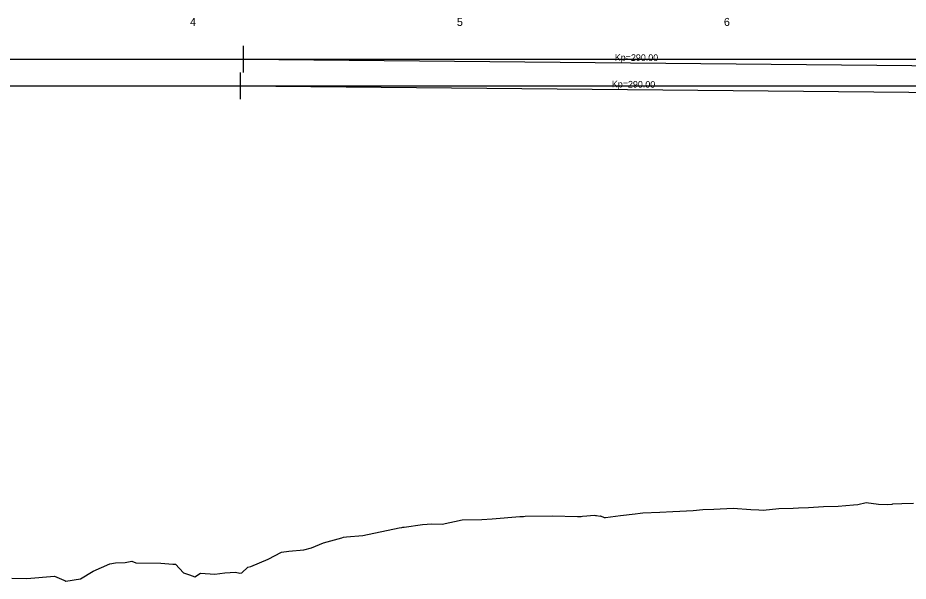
# Model space of a CAD drawing. Extents: x 6531046 to 6533341, y 5514966 to 5518007.
# Drawn here: x 6532180.6 to 6532514.2, y 5516249.9 to 5516461 of the extents above; entities that cross this region are included whole.
import ezdxf

# ---------------------------------------------------------------- set-up
doc = ezdxf.new("R2010")
doc.units = 0
for name, color, linetype in [('IR_default', 7, 'Continuous'), ('TOR_PROF-tabelka-geometria T1', 7, 'Continuous'), ('TOR_PROF-tabelka-kilometracja', 7, 'Continuous')]:
    doc.layers.add(name, color=color, linetype=linetype)

msp = doc.modelspace()

# ---------------------------------------------------------------- linework, layer by layer
at = {"layer": 'IR_default'}
msp.add_lwpolyline([(6532178.4, 5516251.04), (6532183.99, 5516250.9), (6532194.36, 5516251.73), (6532197.81, 5516250.25), (6532198.22, 5516250.12), (6532198.67, 5516249.9), (6532204.05, 5516250.79), (6532204.09, 5516250.8), (6532204.11, 5516250.81), (6532208.83, 5516253.7), (6532215.05, 5516256.47), (6532217.25, 5516256.73), (6532220.8, 5516256.88), (6532223.33, 5516257.47), (6532224.88, 5516256.79), (6532234.24, 5516256.65), (6532238.68, 5516256.27), (6532239.75, 5516256.32), (6532242.69, 5516252.99), (6532244.98, 5516252.35), (6532246.96, 5516251.6), (6532249.01, 5516252.89), (6532254.37, 5516252.6), (6532258.13, 5516253), (6532262.21, 5516253.29), (6532263.76, 5516252.97), (6532264.59, 5516253), (6532266.82, 5516255.18), (6532267.91, 5516255.41), (6532274.37, 5516258.16), (6532279.39, 5516260.81), (6532282.15, 5516261.15), (6532287.75, 5516261.62), (6532290.67, 5516262.44), (6532295.16, 5516264.3), (6532301.94, 5516266.19), (6532302.57, 5516266.36), (6532303.78, 5516266.48), (6532309.87, 5516267.01), (6532323.5, 5516269.84), (6532324.5, 5516270.04), (6532324.81, 5516270.12), (6532325.41, 5516270.18), (6532332.22, 5516271.11), (6532335.77, 5516271.36), (6532339.64, 5516271.27), (6532347.04, 5516272.9), (6532347.05, 5516272.9), (6532347.05, 5516272.9), (6532354.46, 5516272.99), (6532358.33, 5516273.25), (6532368.68, 5516274.17), (6532369.36, 5516274.2), (6532370.11, 5516274.2), (6532370.62, 5516274.22), (6532380.88, 5516274.34), (6532390.31, 5516274.2), (6532391.64, 5516274.18), (6532392.11, 5516274.27), (6532393.72, 5516274.36), (6532396.51, 5516274.59), (6532397.01, 5516274.57), (6532397.31, 5516274.56), (6532397.41, 5516274.51), (6532398.77, 5516274.27), (6532398.94, 5516274.39), (6532400.24, 5516273.81), (6532400.74, 5516273.72), (6532406.35, 5516274.55), (6532411.94, 5516275.19), (6532413.76, 5516275.37), (6532414.72, 5516275.46), (6532421.18, 5516275.81), (6532425.99, 5516276.04), (6532428.59, 5516276.11), (6532433.57, 5516276.44), (6532437.27, 5516276.78), (6532441.3, 5516276.84), (6532448.55, 5516277.3), (6532455.2, 5516276.82), (6532458.24, 5516276.64), (6532459.83, 5516276.57), (6532465.65, 5516277.16), (6532471.1, 5516277.3), (6532473.07, 5516277.42), (6532476.84, 5516277.55), (6532482.38, 5516277.84), (6532487.89, 5516277.97), (6532493.66, 5516278.51), (6532495.31, 5516278.68), (6532498.47, 5516279.38), (6532503.05, 5516278.75), (6532506.43, 5516278.6), (6532506.43, 5516278.65), (6532508.3, 5516278.79), (6532508.31, 5516278.84), (6532511.76, 5516279.01), (6532516.21, 5516279.13)], dxfattribs=at)
at = {"layer": 'TOR_PROF-tabelka-geometria T1'}
for points in [[(6532265.12, 5516440.46), (6532265.12, 5516450.46)], [(6531096.02, 5516445.46), (6532265.12, 5516445.46), (6532265.12, 5516445.46), (6532555.12, 5516442.8), (6532555.12, 5516442.8), (6533086.17, 5516442.8), (6533086.17, 5516442.8), (6533096.02, 5516442.89)], [(6531096.02, 5516445.46), (6533096.02, 5516445.46)], [(6532264.02, 5516430.46), (6532264.02, 5516440.46)], [(6531096.02, 5516435.46), (6533096.02, 5516435.46)], [(6531096.02, 5516435.46), (6532264.02, 5516435.46), (6532264.02, 5516435.46), (6532554.02, 5516432.8), (6532554.02, 5516432.8), (6533086.53, 5516432.8), (6533086.53, 5516432.8), (6533096.02, 5516432.88)]]:
    msp.add_lwpolyline(points, dxfattribs=at)

# ---------------------------------------------------------------- texts
for p in [(6532404.24, 5516444.93), (6532403.13, 5516434.93)]:
    msp.add_text('Kp=290.00', height=2.5, rotation=359.4732, dxfattribs=at).set_placement(p)
at = {"layer": 'TOR_PROF-tabelka-kilometracja'}
for s, p in [('4', (6532245.13, 5516457.96)), ('5', (6532345.12, 5516457.96)), ('6', (6532445.13, 5516457.96))]:
    msp.add_text(s, height=3, dxfattribs=at).set_placement(p)

doc.saveas('drawing.dxf')
